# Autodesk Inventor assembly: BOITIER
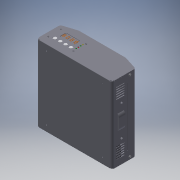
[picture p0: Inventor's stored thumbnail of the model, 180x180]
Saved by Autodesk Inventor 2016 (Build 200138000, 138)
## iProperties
Created: 2011-01
Part Number: BOITIER
Document SubType Name: Assembly
Designer: eric
Mass: 1354.24 g
Surface Area: 8423.69 cm^2
Volume: 1354.24 cm^3
Density: 1 g/cm^3
Norme de conversion: IGES 5.3
Nom du fichier: No Iges File Name specified
Préprocesseur: Autodesk Inventor 2011
Postprocesseur: Build: 342, Release: 2008 SP3 - Date: Tue 05/27/2008
Unités envoyées: MM
Incertitude: 0.01
Author: eric
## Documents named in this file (41)
- \\DC1-0210006T\TSTIDD - Ressources\activité 3 projecteur e-move\projecteurimov\BOITIER.iam
- \\DC1-0210006T\TSTIDD - Ressources\activité 3 projecteur e-move\projecteurimov\fond_boitier.ipt
- \\DC1-0210006T\TSTIDD - Ressources\activité 3 projecteur e-move\projecteurimov\ECROU.ipt
- \\DC1-0210006T\TSTIDD - Ressources\activité 3 projecteur e-move\projecteurimov\ventilo.ipt
- \\DC1-0210006T\TSTIDD - Ressources\activité 3 projecteur e-move\projecteurimov\grille_ventilateur.iam
- \\DC1-0210006T\TSTIDD - Ressources\activité 3 projecteur e-move\projecteurimov\Raccord_alimentation.ipt
- \\DC1-0210006T\TSTIDD - Ressources\activité 3 projecteur e-move\projecteurimov\support_micro.ipt
- \\DC1-0210006T\TSTIDD - Ressources\activité 3 projecteur e-move\projecteurimov\Corniere_superieure.ipt
- \\DC1-0210006T\TSTIDD - Ressources\activité 3 projecteur e-move\projecteurimov\Corniere_angle_Défaut.ipt
- \\DC1-0210006T\TSTIDD - Ressources\activité 3 projecteur e-move\projecteurimov\Corniere_angle.ipt
- \\DC1-0210006T\TSTIDD - Ressources\activité 3 projecteur e-move\projecteurimov\Demi_couvercle.ipt
- \\DC1-0210006T\TSTIDD - Ressources\activité 3 projecteur e-move\projecteurimov\TRAVERSE.ipt
- \\DC1-0210006T\TSTIDD - Ressources\activité 3 projecteur e-move\projecteurimov\SymétrieTRAVERSE.ipt
- \\DC1-0210006T\TSTIDD - Ressources\activité 3 projecteur e-move\projecteurimov\traverse_sup.ipt
- \\DC1-0210006T\TSTIDD - Ressources\activité 3 projecteur e-move\projecteurimov\STATOR.iam
- \\DC1-0210006T\TSTIDD - Ressources\activité 3 projecteur e-move\projecteurimov\Axe_arceau_mobile.ipt
- \\DC1-0210006T\TSTIDD - Ressources\activité 3 projecteur e-move\projecteurimov\plaque_moteur_pan.ipt
- \\DC1-0210006T\TSTIDD - Ressources\activité 3 projecteur e-move\projecteurimov\entretoise_carte.ipt
- \\DC1-0210006T\TSTIDD - Ressources\activité 3 projecteur e-move\projecteurimov\carte_affichage.iam
- \\DC1-0210006T\TSTIDD - Ressources\activité 3 projecteur e-move\projecteurimov\Silent_bloc_moteur.ipt
- \\DC1-0210006T\TSTIDD - Ressources\activité 3 projecteur e-move\projecteurimov\Joint amortisseur.ipt
- \\DC1-0210006T\TSTIDD - Ressources\activité 3 projecteur e-move\projecteurimov\renfort.ipt
- \\DC1-0210006T\TSTIDD - Ressources\activité 3 projecteur e-move\projecteurimov\ISO 4029 - M4 x 6-N.ipt
- \\DC1-0210006T\TSTIDD - Ressources\activité 3 projecteur e-move\projecteurimov\Vis Tapping Screw ISO 14585 - ST4.8x 3.7-C-S.ipt
- \\DC1-0210006T\TSTIDD - Ressources\activité 3 projecteur e-move\projecteurimov\Vis ISO 7045 - M4 x 10 - Z --- 10C.ipt
- \\DC1-0210006T\TSTIDD - Ressources\activité 3 projecteur e-move\projecteurimov\rivet_colle_M3_2.ipt
- \\DC1-0210006T\TSTIDD - Ressources\activité 3 projecteur e-move\projecteurimov\rivet_colle.ipt
- \\DC1-0210006T\TSTIDD - Ressources\activité 3 projecteur e-move\projecteurimov\Vis ISO 7045 - M3 x 5 - Z --- 5C.ipt
- \\DC1-0210006T\TSTIDD - Ressources\activité 3 projecteur e-move\projecteurimov\Rondelle ISO 7093 - 3.ipt
- \\DC1-0210006T\TSTIDD - Ressources\activité 3 projecteur e-move\projecteurimov\Ecrou ISO 7040-M3-N_ISO 7040-M3-N.ipt
- \\DC1-0210006T\TSTIDD - Ressources\activité 3 projecteur e-move\projecteurimov\Ecrou ISO 7040-M3-N.ipt
- \\DC1-0210006T\TSTIDD - Ressources\activité 3 projecteur e-move\projecteurimov\Rondelle ISO 7093 - 3_Washer ISO 7093 - 3.ipt
- \\DC1-0210006T\TSTIDD - Ressources\activité 3 projecteur e-move\projecteurimov\Ecrou_arceau.ipt
- \\DC1-0210006T\TSTIDD - Ressources\activité 3 projecteur e-move\projecteurimov\cylindre amortisseur.ipt
- \\DC1-0210006T\TSTIDD - Ressources\activité 3 projecteur e-move\projecteurimov\circuit commande.ipt
- \\DC1-0210006T\TSTIDD - Ressources\activité 3 projecteur e-move\projecteurimov\transformateur.ipt
- \\DC1-0210006T\TSTIDD - Ressources\activité 3 projecteur e-move\projecteurimov\neutrik xlr femelle.ipt
- \\DC1-0210006T\TSTIDD - Ressources\activité 3 projecteur e-move\projecteurimov\neutrik xlr male.ipt
- \\DC1-0210006T\TSTIDD - Ressources\activité 3 projecteur e-move\projecteurimov\vis_butee.ipt
- \\DC1-0210006T\TSTIDD - Ressources\activité 3 projecteur e-move\projecteurimov\micro_contact.ipt
- \\DC1-0210006T\TSTIDD - Ressources\activité 3 projecteur e-move\projecteurimov\courroie pan.ipt
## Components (85 placed, 40 different names)
1. fond_boitier:1
2. ECROU:1
3. ECROU:2
4. ECROU:3
5. ECROU:4
6. ventilo:1
7. grille_ventilateur:1 [sub-assembly]
8. Raccord_alimentation:1
9. support_micro:1
10. Corniere_superieure:1
11. Corniere_superieure:2
12. Corniere_angle_Défaut:1
13. Corniere_angle_Défaut:2
14. Corniere_angle:1
15. Corniere_angle:2
16. Demi_couvercle:1
17. Demi_couvercle:2
18. TRAVERSE:1
19. SymétrieTRAVERSE:1
20. traverse_sup:1
21. STATOR:1 [sub-assembly]
22. Axe_arceau_mobile:1
23. plaque_moteur_pan:1
24. entretoise_carte:1
25. entretoise_carte:2
26. entretoise_carte:3
27. entretoise_carte:4
28. carte_affichage:1 [sub-assembly]
29. Silent_bloc_moteur:1
30. Silent_bloc_moteur:2
31. Silent_bloc_moteur:3
32. Silent_bloc_moteur:4
33. Joint amortisseur:1
34. renfort:1
35. renfort:2
36. renfort:3
37. renfort:4
38. ISO 4029 - M4 x 6-N:1
39. Vis Tapping Screw ISO 14585 - ST4.8x 3.7-C-S:1
40. Vis Tapping Screw ISO 14585 - ST4.8x 3.7-C-S:2
41. Vis Tapping Screw ISO 14585 - ST4.8x 3.7-C-S:3
42. Vis Tapping Screw ISO 14585 - ST4.8x 3.7-C-S:4
43. Vis ISO 7045 - M4 x 10 - Z --- 10C:1
44. Vis ISO 7045 - M4 x 10 - Z --- 10C:2
45. Vis ISO 7045 - M4 x 10 - Z --- 10C:3
46. Vis ISO 7045 - M4 x 10 - Z --- 10C:4
47. rivet_colle_M3_2:1
48. rivet_colle_M3_2:2
49. rivet_colle:1
50. rivet_colle:2
51. rivet_colle:3
52. rivet_colle:4
53. rivet_colle:5
54. rivet_colle:6
55. rivet_colle:7
56. rivet_colle:8
57. Vis ISO 7045 - M4 x 10 - Z --- 10C:5
58. Vis ISO 7045 - M4 x 10 - Z --- 10C:6
59. Vis ISO 7045 - M4 x 10 - Z --- 10C:7
60. Vis ISO 7045 - M4 x 10 - Z --- 10C:8
61. Vis ISO 7045 - M3 x 5 - Z --- 5C:1
62. Vis ISO 7045 - M3 x 5 - Z --- 5C:2
63. Rondelle ISO 7093 - 3:1
64. Rondelle ISO 7093 - 3:2
65. Rondelle ISO 7093 - 3:3
66. Rondelle ISO 7093 - 3:4
67. Ecrou ISO 7040-M3-N_ISO 7040-M3-N:1
68. Ecrou ISO 7040-M3-N:1
69. Ecrou ISO 7040-M3-N:2
70. Ecrou ISO 7040-M3-N:3
71. Rondelle ISO 7093 - 3_Washer ISO 7093 - 3:1
72. Rondelle ISO 7093 - 3:5
73. Rondelle ISO 7093 - 3:6
74. Rondelle ISO 7093 - 3:7
75. Ecrou_arceau:1
76. cylindre amortisseur:1
77. cylindre amortisseur:2
78. circuit commande:1
79. transformateur:1
80. neutrik xlr femelle:1
81. neutrik xlr male:1
82. vis_butee:1
83. vis_butee:2
84. courroie pan:1
85. micro_contact:1
